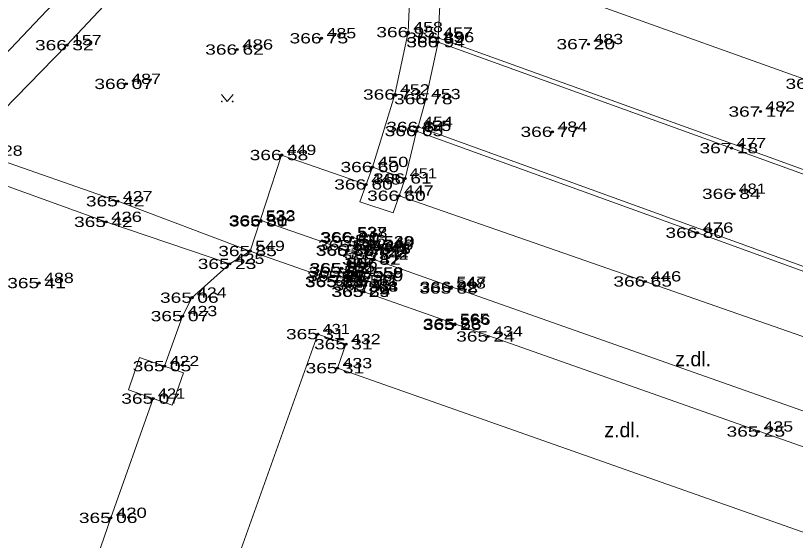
# Model space of a CAD drawing. Extents: x -789669 to -789458, y -977587 to -977420.
# Drawn here: x -789622.4 to -789569.1, y -977530.3 to -977494.5 of the extents above; entities that cross this region are included whole.
import ezdxf
from ezdxf.enums import TextEntityAlignment as Align

# ---------------------------------------------------------------- set-up
doc = ezdxf.new("R2010")
doc.units = 0
doc.header["$LTSCALE"] = 0.28
doc.header["$PDMODE"] = 32
doc.header["$PDSIZE"] = 0.14
doc.layers.add('1', color=7, linetype='Continuous', lineweight=13)
doc.layers.add('4', color=7, linetype='Continuous', lineweight=13)
for name, color, linetype in [('5', 7, 'Continuous'), ('57', 7, 'Continuous'), ('58', 7, 'Continuous'), ('59', 7, 'Continuous')]:
    doc.layers.add(name, color=color, linetype=linetype)

msp = doc.modelspace()

# ---------------------------------------------------------------- linework, layer by layer
at = {"layer": '1'}
for p, q in [((-789598.89, -977507.2), (-789598.46, -977506.01)), ((-789598.89, -977507.2), (-789596.62, -977507.96)), ((-789599.506, -977509.861), (-789597.672, -977510.486)), ((-789599.603, -977510.148), (-789597.781, -977510.777)), ((-789600.243, -977511.982), (-789598.377, -977512.638)), ((-789600.338, -977512.27), (-789598.478, -977512.918)), ((-789613.949, -977517.846), (-789614.708, -977520.053)), ((-789614.708, -977520.053), (-789611.718, -977521.095))]:
    msp.add_line(p, q, dxfattribs=at)
for points in [[(-789601.64, -977464.89), (-789599.95, -977466.17), (-789598.64, -977467.75), (-789598.59, -977469.78), (-789599.16, -977471.77), (-789600.59, -977473.55), (-789609.94, -977483.26), (-789619.88, -977493.69), (-789629.88, -977504.18), (-789634.89, -977509.42), (-789637.37, -977512.43)], [(-789624.85, -977503.61), (-789625.01, -977502.71), (-789618.92, -977496.49), (-789609.22, -977486.14), (-789603.75, -977480.49), (-789602.26, -977483.1), (-789598.63, -977486.58)], [(-789593.53, -977495.98), (-789593.36, -977492.41), (-789593.57, -977489.74), (-789594.41, -977485.98), (-789594.41, -977484.36), (-789594.41, -977484.36), (-789593.98, -977483.62), (-789593.2, -977483.26)], [(-789598.63, -977486.58), (-789596.03, -977487.78), (-789595.46, -977492.43), (-789595.58, -977495.6), (-789596.49, -977499.86), (-789598.03, -977504.82)], [(-789555.4, -977503.56), (-789567.6, -977499.13), (-789583.03, -977493.61), (-789593.57, -977489.74)], [(-789594.9, -977502.08), (-789594.37, -977500.18), (-789593.53, -977496.29), (-789593.53, -977495.98)], [(-789593.53, -977495.98), (-789573.48, -977503.22), (-789558.267, -977508.722)], [(-789593.53, -977496.29), (-789573.48, -977503.53), (-789558.41, -977508.98)], [(-789595.8, -977505.6), (-789595.01, -977502.36), (-789594.9, -977502.08)], [(-789595.01, -977502.36), (-789575.81, -977509.31), (-789560.62, -977514.82), (-789546.79, -977519.85)], [(-789594.9, -977502.08), (-789575.7, -977509.03), (-789560.51, -977514.54), (-789546.68, -977519.57)], [(-789624.85, -977503.61), (-789624.32, -977504.05), (-789615.44, -977507.16), (-789606.39, -977510.56)], [(-789600.46, -977512.64), (-789606.39, -977510.56), (-789604.24, -977504), (-789598.46, -977506.01)], [(-789607.79, -977511.44), (-789616.25, -977508.57), (-789626.18, -977504.99)], [(-789598.46, -977506.01), (-789598.03, -977504.82), (-789595.8, -977505.6), (-789596.21, -977506.78), (-789596.62, -977507.96)], [(-789596.21, -977506.78), (-789579.37, -977512.64), (-789563.76, -977518.1)], [(-789605.7, -977508.456), (-789599.73, -977510.52), (-789599.42, -977509.61), (-789597.58, -977510.24)], [(-789597.58, -977510.24), (-789597.92, -977511.15), (-789592.62, -977513.01), (-789551.29, -977527.58)], [(-789612.24, -977518.43), (-789611.01, -977515.01), (-789610.37, -977513.75), (-789607.79, -977511.44), (-789606.39, -977510.56)], [(-789600.46, -977512.64), (-789600.16, -977511.73), (-789598.28, -977512.37), (-789598.63, -977513.34)], [(-789552.95, -977529.45), (-789592.39, -977515.54), (-789598.63, -977513.34)], [(-789613.949, -977517.846), (-789610.959, -977518.887), (-789611.718, -977521.095)], [(-789618.082, -977544.746), (-789619.37, -977538.78), (-789615.92, -977528.8), (-789613.02, -977520.65)]]:
    msp.add_lwpolyline(points, dxfattribs=at)
msp.add_lwpolyline([(-789610.77, -977541.45), (-789601.76, -977516.24), (-789599.84, -977516.93), (-789600.42, -977518.57), (-789557, -977533.86), (-789556.41, -977532.23), (-789554.54, -977532.86), (-789563.4, -977558.1)], close=True, dxfattribs=at)
at = {"layer": '4'}
for points in [[(-789608.363, -977499.857), (-789607.961, -977500.336), (-789607.559, -977499.857)], [(-789608.335, -977500.313), (-789608.321, -977500.321), (-789608.316, -977500.336), (-789608.322, -977500.349), (-789608.335, -977500.357), (-789608.351, -977500.349), (-789608.357, -977500.336), (-789608.353, -977500.322), (-789608.342, -977500.316), (-789608.327, -977500.322), (-789608.322, -977500.336), (-789608.325, -977500.346), (-789608.335, -977500.351), (-789608.346, -977500.346), (-789608.352, -977500.335), (-789608.347, -977500.325), (-789608.342, -977500.322), (-789608.331, -977500.326), (-789608.326, -977500.336), (-789608.332, -977500.343), (-789608.34, -977500.341), (-789608.345, -977500.333), (-789608.34, -977500.328), (-789608.332, -977500.332), (-789608.335, -977500.336)], [(-789607.585, -977500.314), (-789607.571, -977500.322), (-789607.566, -977500.337), (-789607.572, -977500.35), (-789607.585, -977500.358), (-789607.601, -977500.35), (-789607.607, -977500.337), (-789607.603, -977500.323), (-789607.592, -977500.317), (-789607.577, -977500.323), (-789607.572, -977500.337), (-789607.575, -977500.347), (-789607.585, -977500.352), (-789607.596, -977500.347), (-789607.602, -977500.336), (-789607.597, -977500.326), (-789607.592, -977500.323), (-789607.581, -977500.327), (-789607.576, -977500.337), (-789607.582, -977500.344), (-789607.59, -977500.342), (-789607.595, -977500.334), (-789607.59, -977500.329), (-789607.582, -977500.333), (-789607.585, -977500.337)]]:
    msp.add_lwpolyline(points, dxfattribs=at)
for centre in [(-789608.336, -977500.336), (-789607.586, -977500.336)]:
    msp.add_circle(centre, 0.025, dxfattribs=at)
at = {"layer": '57'}
for p in [(-789595.58, -977495.6), (-789601.51, -977496.02), (-789593.53, -977495.98), (-789618.92, -977496.49), (-789593.53, -977496.29), (-789583.26, -977496.42), (-789607.28, -977496.79), (-789614.86, -977499.14), (-789596.49, -977499.86), (-789594.37, -977500.18), (-789571.5, -977501.03), (-789595.01, -977502.36), (-789594.9, -977502.08), (-789585.72, -977502.41), (-789573.48, -977503.53), (-789604.24, -977504), (-789598.03, -977504.82), (-789595.8, -977505.6), (-789598.46, -977506.01), (-789596.21, -977506.78), (-789573.31, -977506.65), (-789615.44, -977507.16), (-789616.25, -977508.57), (-789605.67, -977508.53), (-789605.66, -977508.47), (-789575.81, -977509.31), (-789599.42, -977509.61), (-789599.38, -977509.65), (-789606.39, -977510.56), (-789599.73, -977510.52), (-789599.71, -977510.54), (-789599.57, -977510.16), (-789597.69, -977510.48), (-789597.61, -977510.26), (-789597.58, -977510.24), (-789597.8, -977510.77), (-789597.78, -977510.75), (-789597.78, -977510.76), (-789607.79, -977511.44), (-789597.93, -977511.15), (-789597.92, -977511.15), (-789600.22, -977511.99), (-789600.16, -977511.73), (-789600.13, -977511.75), (-789600.46, -977512.64), (-789600.46, -977512.68), (-789600.31, -977512.28), (-789598.4, -977512.63), (-789598.32, -977512.4), (-789598.28, -977512.37), (-789579.37, -977512.64), (-789620.82, -977512.75), (-789598.5, -977512.91), (-789592.64, -977513.12), (-789592.62, -977513.01), (-789610.37, -977513.75), (-789598.66, -977513.35), (-789598.63, -977513.34), (-789611.01, -977515.01), (-789592.41, -977515.61), (-789592.39, -977515.54), (-789601.76, -977516.24), (-789590.12, -977516.4), (-789599.84, -977516.93), (-789612.24, -977518.43), (-789600.42, -977518.57), (-789613.02, -977520.65), (-789571.63, -977522.9), (-789615.92, -977528.8)]:
    msp.add_point(p, dxfattribs=at)

# ---------------------------------------------------------------- texts
at = {"layer": '5'}
for p in [(-789577.327, -977518.437), (-789582.173, -977523.288)]:
    msp.add_text('z.dl.', height=1, dxfattribs=at).set_placement(p)
at = {"layer": '58'}
for s, width, p in [(' 458', 1.3, (-789595.58, -977495.6)), (' 485', 1.3, (-789601.51, -977496.02)), (' 457', 1.3, (-789593.53, -977495.98)), (' 456', 1.35, (-789593.53, -977496.29)), (' 157', 1.3, (-789618.92, -977496.49)), (' 486', 1.35, (-789607.28, -977496.79)), (' 483', 1.3, (-789583.26, -977496.42)), (' 487', 1.3, (-789614.86, -977499.14)), (' 452', 1.3, (-789596.49, -977499.86)), (' 453', 1.3, (-789594.37, -977500.18)), (' 482', 1.3, (-789571.5, -977501.03)), (' 454', 1.3, (-789594.9, -977502.08)), (' 455', 1.3, (-789595.01, -977502.36)), (' 484', 1.3, (-789585.72, -977502.41)), (' 477', 1.3, (-789573.48, -977503.53)), (' 428', 1.3, (-789624.32, -977504.05)), (' 449', 1.3, (-789604.24, -977504)), (' 450', 1.35, (-789598.03, -977504.82)), (' 451', 1.2, (-789595.8, -977505.6)), (' 448', 1.3, (-789598.46, -977506.01)), (' 447', 1.3, (-789596.21, -977506.78)), (' 481', 1.2, (-789573.31, -977506.65)), (' 427', 1.3, (-789615.44, -977507.16)), (' 533', 1.3, (-789605.67, -977508.53)), (' 532', 1.3, (-789605.66, -977508.47)), (' 426', 1.35, (-789616.25, -977508.57)), (' 537', 1.3, (-789599.42, -977509.61)), (' 476', 1.35, (-789575.81, -977509.31)), (' 538', 1.3, (-789599.38, -977509.65)), (' 549', 1.3, (-789606.39, -977510.56)), (' 534', 1.3, (-789599.73, -977510.52)), (' 535', 1.3, (-789599.71, -977510.54)), (' 536', 1.35, (-789599.57, -977510.16)), (' 546', 1.35, (-789597.69, -977510.48)), (' 540', 1.35, (-789597.61, -977510.26)), (' 539', 1.3, (-789597.58, -977510.24)), (' 544', 1.3, (-789597.93, -977511.15)), (' 542', 1.3, (-789597.92, -977511.15)), (' 541', 1.2, (-789597.8, -977510.77)), (' 543', 1.3, (-789597.78, -977510.76)), (' 545', 1.3, (-789597.78, -977510.75)), (' 425', 1.3, (-789607.79, -977511.44)), (' 557', 1.3, (-789600.16, -977511.73)), (' 556', 1.35, (-789600.13, -977511.75)), (' 555', 1.3, (-789600.22, -977511.99)), (' 488', 1.3, (-789620.82, -977512.75)), (' 551', 1.2, (-789600.46, -977512.64)), (' 552', 1.3, (-789600.46, -977512.68)), (' 554', 1.3, (-789600.31, -977512.28)), (' 560', 1.35, (-789598.4, -977512.63)), (' 559', 1.3, (-789598.32, -977512.4)), (' 558', 1.3, (-789598.28, -977512.37)), (' 446', 1.35, (-789579.37, -977512.64)), (' 564', 1.3, (-789598.66, -977513.35)), (' 563', 1.3, (-789598.63, -977513.34)), (' 561', 1.2, (-789598.5, -977512.91)), (' 548', 1.3, (-789592.64, -977513.12)), (' 547', 1.3, (-789592.62, -977513.01)), (' 424', 1.3, (-789610.37, -977513.75)), (' 423', 1.3, (-789611.01, -977515.01)), (' 566', 1.35, (-789592.41, -977515.61)), (' 565', 1.3, (-789592.39, -977515.54)), (' 431', 1.2, (-789601.76, -977516.24)), (' 434', 1.3, (-789590.12, -977516.4)), (' 432', 1.3, (-789599.84, -977516.93)), (' 422', 1.3, (-789612.24, -977518.43)), (' 433', 1.3, (-789600.42, -977518.57)), (' 421', 1.2, (-789613.02, -977520.65)), (' 435', 1.3, (-789571.63, -977522.9)), (' 420', 1.35, (-789615.92, -977528.8))]:
    msp.add_text(s, height=0.7, dxfattribs=dict(at, width=width)).set_placement(p)
at = {"layer": '59', "width": 1.4}
for s, p in [('366 95 ', (-789595.58, -977495.95)), ('366 75 ', (-789601.51, -977496.37)), ('366 89 ', (-789593.53, -977496.33)), ('366 94 ', (-789593.53, -977496.64)), ('367 20 ', (-789583.26, -977496.77)), ('366 32 ', (-789618.92, -977496.84)), ('366 62 ', (-789607.28, -977497.14)), ('366 07 ', (-789614.86, -977499.49)), ('367 49 ', (-789567.6, -977499.48)), ('366 73 ', (-789596.49, -977500.21)), ('366 78 ', (-789594.37, -977500.53)), ('367 17 ', (-789571.5, -977501.38)), ('366 64 ', (-789594.9, -977502.43)), ('366 65 ', (-789595.01, -977502.71)), ('366 77 ', (-789585.72, -977502.76)), ('367 18 ', (-789573.48, -977503.88)), ('366 58 ', (-789604.24, -977504.35)), ('366 60 ', (-789598.03, -977505.17)), ('366 60 ', (-789598.46, -977506.36)), ('366 61 ', (-789595.8, -977505.95)), ('366 60 ', (-789596.21, -977507.13)), ('366 84 ', (-789573.31, -977507)), ('365 42 ', (-789615.44, -977507.51)), ('365 42 ', (-789616.25, -977508.92)), ('365 80 ', (-789605.67, -977508.88)), ('366 31 ', (-789605.66, -977508.82)), ('366 41 ', (-789599.42, -977509.96)), ('366 20 ', (-789599.38, -977510)), ('366 80 ', (-789575.81, -977509.66)), ('365 88 ', (-789599.57, -977510.51)), ('366 19 ', (-789597.61, -977510.61)), ('366 44 ', (-789597.58, -977510.59)), ('365 85 ', (-789606.39, -977510.91)), ('366 35 ', (-789599.73, -977510.87)), ('365 86 ', (-789599.71, -977510.89)), ('365 87 ', (-789597.8, -977511.12)), ('366 02 ', (-789597.78, -977511.1)), ('366 02 ', (-789597.78, -977511.11)), ('366 18 ', (-789597.69, -977510.83)), ('365 87 ', (-789597.93, -977511.5)), ('366 42 ', (-789597.92, -977511.5)), ('365 23 ', (-789607.79, -977511.79)), ('365 83 ', (-789600.16, -977512.08)), ('365 62 ', (-789600.13, -977512.1)), ('365 45 ', (-789600.31, -977512.63)), ('365 61 ', (-789600.22, -977512.34)), ('365 62 ', (-789598.32, -977512.75)), ('365 83 ', (-789598.28, -977512.72)), ('365 41 ', (-789620.82, -977513.1)), ('365 83 ', (-789600.46, -977512.99)), ('365 29 ', (-789600.46, -977513.03)), ('365 45 ', (-789598.5, -977513.26)), ('365 61 ', (-789598.4, -977512.98)), ('366 65 ', (-789579.37, -977512.99)), ('365 29 ', (-789598.66, -977513.7)), ('365 84 ', (-789598.63, -977513.69)), ('365 88 ', (-789592.64, -977513.47)), ('366 42 ', (-789592.62, -977513.36)), ('365 06 ', (-789610.37, -977514.1)), ('365 07 ', (-789611.01, -977515.36)), ('365 26 ', (-789592.41, -977515.96)), ('365 83 ', (-789592.39, -977515.89)), ('365 31 ', (-789601.76, -977516.59)), ('365 24 ', (-789590.12, -977516.75)), ('365 31 ', (-789599.84, -977517.28)), ('365 05 ', (-789612.24, -977518.78)), ('365 31 ', (-789600.42, -977518.92)), ('365 07 ', (-789613.02, -977521)), ('365 25 ', (-789571.63, -977523.25)), ('365 06 ', (-789615.92, -977529.15))]:
    msp.add_text(s, height=0.7, dxfattribs=at).set_placement(p, align=Align.CENTER)

doc.saveas('drawing.dxf')
